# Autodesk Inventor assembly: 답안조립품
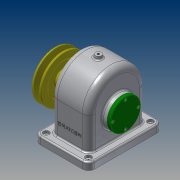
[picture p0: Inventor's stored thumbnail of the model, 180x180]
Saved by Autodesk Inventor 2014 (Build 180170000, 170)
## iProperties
Created: 2016-10
Part Number: 답안조립품
Document SubType Name: Assembly
Designer: USER
Author: USER
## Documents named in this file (15)
- C:\Users\USER\Desktop\461008V1013\답안조립품.iam
- C:\Users\USER\Desktop\461008V1013\본체.ipt
- C:\Users\USER\Desktop\461008V1013\뒤커버.ipt
- C:\Users\USER\Desktop\461008V1013\앞커버.ipt
- C:\Users\USER\Desktop\461008V1013\베어링 6203.ipt
- C:\Users\USER\Desktop\461008V1013\축.ipt
- C:\Users\USER\Desktop\461008V1013\부시.ipt
- C:\Users\USER\Desktop\461008V1013\오일씰 28 40 8.ipt
- C:\Users\USER\Desktop\461008V1013\스퍼기어.ipt
- C:\Users\USER\Desktop\461008V1013\키 - 6 x 6 x 22.ipt
- C:\Users\USER\Desktop\461008V1013\볼트 M3 x 8.ipt
- C:\Users\USER\Desktop\461008V1013\볼트 M3 x 10.ipt
- C:\Users\USER\Desktop\461008V1013\V-벨트풀리.ipt
- C:\Users\USER\Desktop\461008V1013\멈춤나사 - M4x10.ipt
- C:\Users\USER\Desktop\461008V1013\키 - 5 x 5 x 18.ipt
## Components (9 placed, 3 different names)
1. V-벨트풀리:1
2. ISO 4762 M3 x 8:1
3. ISO 4762 M3 x 8:2
4. ISO 4762 M3 x 8:3
5. ISO 4762 M3 x 8:4
6. ISO 4762 M3 x 10:1
7. ISO 4762 M3 x 10:2
8. ISO 4762 M3 x 10:3
9. ISO 4762 M3 x 10:4
